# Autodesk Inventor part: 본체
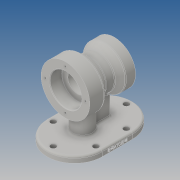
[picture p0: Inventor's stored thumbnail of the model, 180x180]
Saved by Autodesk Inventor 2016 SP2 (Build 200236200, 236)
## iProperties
Created: 2020-01
Part Number: 본체
Material: Generic
Document SubType Name: Modeling
Designer: EZ
Density: 1 g/cm^3
Appearance: Default
Author: EZ
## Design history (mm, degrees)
sketch "스케치1"
  geometry: L1 (0, 25)-(0, -25); L2 (-45, 25)-(-45, -25); L3 (45, -25)-(45, 25); A1 r 45 centre (0, 25) between (45, 25) and (-45, 25); A2 r 45 centre (0, -25) between (-45, -25) and (45, -25); 2 further points
  constraints: 8 end point, 4 point on circle, 4 tangent, 2 centre point, 2 coincident, 1 midpoint, 1 parallel, 1 vertical
  dimensions: "d0" = 50 distance of L1.end L1.start; "d1" = 45 radius of A1
extrude "돌출1" new body sketch "스케치1" distance "d2" = 10; taper "d3" = 0 deg
sketch "스케치2"
  geometry: L1 (120, 40)-(80, 40); L2 (80, 40)-(80, 16); L3 (80, 16)-(120, 16); L4 (120, 16)-(120, 40); L5 (115, -24)-(80, -24); L6 (80, -24)-(80, -40); L7 (80, -40)-(115, -40); L8 (115, -40)-(115, -24); L9 (10, -70)-(0, -70) reference; L10 (0, -70)-(0, 70) reference; L11 (0, 70)-(10, 70) reference; L12 (10, 70)-(10, -70) reference; L13 (107.5, 1.103)-(80, 1.103); L14 (80, 1.103)-(80, -13.289); L15 (80, -13.289)-(107.5, -13.289); L16 (107.5, -13.289)-(107.5, 1.103); L17 (107.5, -13.289)-(115, -24); L18 (107.5, 1.103)-(120, 16); L19 (80, 16)-(80, 1.103); L20 (80, -13.289)-(80, -24); 1 further point
  constraints: 32 end point, 6 parallel, 3 horizontal, 3 perpendicular, 1 collinear
  dimensions: "d4" = 80 distance from line of point (0, 0) L2; "d5" = 80 distance from line of point (0, 0) L6; "d6" = 80 diameter of L4 L2; "d7" = 24 distance between parallel lines of L3 L1; "d8" = 70 diameter of L8 L6; "d9" = 16 distance between parallel lines of L5 L7; "d10" = 30 distance between parallel lines of L11 L1; "d11" = 80 distance between parallel lines of L1 L7; "d12" = 55 diameter of L16 L14; "d13" = 40 deg angle of L16 L18; "d14" = 35 deg angle of L16 L17
revolve "회전1" sketch "스케치2" stored, may be unused: angle "d15" = 90 deg
sketch "스케치3"
  geometry: L1 (-45, -25)-(-45, 25) reference; L2 (45, 25)-(45, -25) reference; L3 (0, -70)-(66.928, -70); C1 r 16 at (0, -12); A1 r 45 centre (0, -25) between (-45, -25) and (45, -25) reference; A2 r 45 centre (0, 25) between (45, 25) and (-45, 25) reference; 2 further points
  constraints: 2 end point, 1 centre point, 1 coincident, 1 horizontal, 1 point on circle, 1 tangent
  dimensions: "d16" = 58 distance from line of point (0, -12) L3; "d17" = 32 diameter of C1
extrude "돌출2" join sketch "스케치3" stored distance "d18" = 0; taper "d19" = 0 deg
sketch "스케치4"
  geometry: L1 (10, -70)-(0, -70) reference; L2 (0, -70)-(0, 70) reference; L3 (0, 70)-(10, 70) reference; L4 (10, 70)-(10, 28) reference; L5 (10, 28)-(40, 28) reference; L6 (40, 28)-(40, 40) reference; L7 (40, 40)-(120, 40) reference; L8 (120, 40)-(120, 16) reference; L9 (120, 16)-(107.5, 1.103) reference; L10 (107.5, 1.103)-(107.5, -13.289) reference; L11 (107.5, -13.289)-(115, -24) reference; L12 (115, -24)-(115, -40) reference; L13 (115, -40)-(45, -40) reference; L14 (45, -40)-(45, -24) reference; L15 (45, -24)-(52.5, -13.289) reference; L16 (52.5, -13.289)-(52.5, -4) reference; L17 (52.5, -4)-(10, -4) reference; L18 (10, -4)-(10, -70) reference; L19 (45, -30)-(10, -30); 1 further point
  constraints: 2 end point, 2 point on line, 1 perpendicular
  dimensions: "d20" = 10 distance between parallel lines of L13 L19
feature "리브1" sketch "스케치4" dims "d21" = 1, "d22" = 10, "d23" = 0, "d24" = 0, "d25" = 1, "d26" = 1
fillet "모깎기1" dims "d27" = 3
fillet "모깎기2" dims "d28" = 3
sketch "스케치5"
  geometry: C1 r 20 at (0, 0); 1 further point
  constraints: 1 centre point
  dimensions: "d29" = 40 diameter of C1
extrude "돌출3" cut sketch "스케치5" distance "d30" = 17; taper "d31" = 0 deg
sketch "스케치6"
  geometry: C1 r 26 at (0, 0); 1 further point
  constraints: 1 centre point
  dimensions: "d32" = 52 diameter of C1
extrude "돌출4" cut sketch "스케치6" distance "d33" = 20; taper "d34" = 0 deg
sketch "스케치7"
  geometry: C1 r 16 at (0, 0); 1 further point
  constraints: 1 centre point
  dimensions: "d35" = 32 diameter of C1
extrude "돌출5" cut sketch "스케치7" stored distance "d36" = 20; taper "d37" = 0 deg
fillet "모깎기3" dims "d38" = 0.3
sketch "스케치8" dims "d39" = 55
  geometry: 3 further points
  constraints: 1 vertical alignment, 2 other
hole "구멍1" sketch "스케치8" at (0, 27.5) diameter "d40" = 3.242; stored, may be unused: countersink angle "d44" = 90 deg, drill point angle "d46" = 118 deg; dims "d41" = 9, "d42" = 4, "d43" = 2, "d45" = 11
sketch "스케치9" dims "d50" = 66
  geometry: 3 further points
  constraints: 1 vertical alignment, 2 other
hole "구멍2" sketch "스케치9" at (0, 33) diameter "d51" = 3.242; stored, may be unused: countersink angle "d55" = 90 deg, drill point angle "d57" = 118 deg; dims "d52" = 9, "d53" = 4, "d54" = 2, "d56" = 11
chamfer "모따기1" distance "d61" = 1; stored, may be unused: second distance "d62" = 2, angle "d63" = 45 deg
sketch "스케치10"
  geometry: L1 (8, 5.234)-(8, 27) reference; L2 (2, 33)-(-2, 33) reference; L3 (-8, 27)-(-8, 5.234) reference; L4 (-45, -25)-(-45, 25) reference; L5 (45, 25)-(45, -25) reference; L6 (0, -25)-(0, 25); L7 (35, -25)-(35, 25); L8 (-35, 25)-(-35, -25); A1 r 19 centre (0, -12) between (-8, 5.234) and (8, 5.234) reference; A2 r 6 centre (2, 27) between (8, 27) and (2, 33) reference; A3 r 6 centre (-2, 27) between (-2, 33) and (-8, 27) reference; A4 r 45 centre (0, -25) between (-45, -25) and (45, -25) reference; A5 r 45 centre (0, 25) between (45, 25) and (-45, 25) reference; A6 r 35 centre (0, -25) between (-35, -25) and (35, -25); A7 r 35 centre (0, 25) between (35, 25) and (-35, 25); 8 further points
  constraints: 8 end point, 6 point on circle, 4 coincident, 4 tangent, 2 centre point, 1 midpoint, 1 parallel, 1 vertical
  dimensions: "d67" = 35 radius of A7
hole "구멍3" sketch "스케치10" at (0, -60), (35, -25), (35, 25), (0, 60), (-35, -25), (-35, 25) diameter "d68" = 9; stored, may be unused: countersink angle "d72" = 90 deg, drill point angle "d74" = 118 deg; dims "d69" = 9, "d70" = 4, "d71" = 2, "d73" = 11
sketch "스케치11"
  geometry: L1 (50, 0)-(0, 0) reference; L2 (0, 0)-(0, 10) reference; L3 (0, 10)-(50, 10) reference; L4 (50, 0)-(50, 10) reference; L5 (-45, 0)-(-45, 10) reference; 2 further points
  constraints: 1 other
  dimensions: "d75" = 4 distance of point (25, 0) point (25, 4); "d76" = 70 distance from line of L5 point (25, 4)
feature "엠보싱1" sketch "스케치11" dims "d4" = 80, "d5" = 80, "d6" = 80, "d7" = 24, "d8" = 70, "d9" = 16, "d10" = 30, "d11" = 80, "d12" = 55, "d13" = 40 deg, "d14" = 35 deg, "d77" = 0.5, "d78" = 0
fillet "모깎기4" dims "d79" = 3
fillet "모깎기5" dims "d80" = 3
node "솔리드1"
pattern_circular "원형 패턴1" dims angle "d48" = 360 deg
pattern_circular "원형 패턴2" dims angle "d59" = 360 deg
node "절단 모서리 투영1"
node "절단 모서리 투영2"
node "절단 모서리 투영3"
node "절단 모서리 투영4"
node "절단 모서리 투영5"
